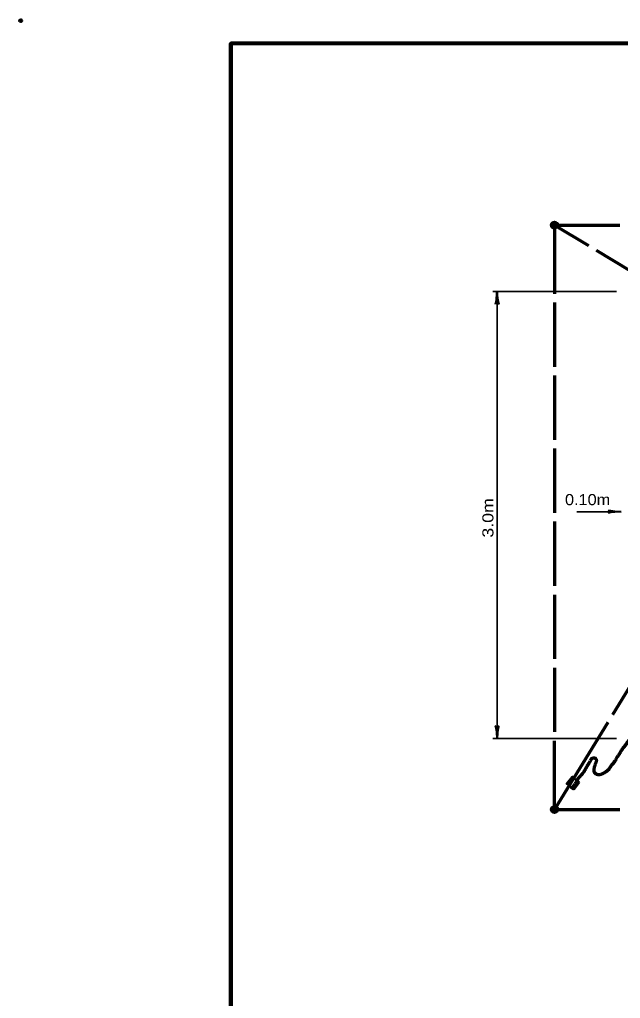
# Model space of a CAD drawing. Extents: x -30 to 826, y -11 to 533.
# Drawn here: x -29.8 to 133.1, y 268.1 to 533.4 of the extents above; entities that cross this region are included whole.
import ezdxf

# ---------------------------------------------------------------- set-up
doc = ezdxf.new("R2010")
doc.units = 0
doc.header["$LTSCALE"] = 1.2
doc.header["$PDMODE"] = 32
doc.header["$PDSIZE"] = 0.6
doc.layers.add('1', color=7, linetype='Continuous', lineweight=53)

msp = doc.modelspace()

# ---------------------------------------------------------------- hatches: boundary and pattern name
at = {"layer": '1'}
for points in [[(116.199, 477.732, 1), (114.399, 477.732, 1)], [(116.199, 319.332, 1), (114.399, 319.332, 1)]]:
    msp.add_hatch(color=256, dxfattribs=at).paths.add_polyline_path(points)

# ---------------------------------------------------------------- linework, layer by layer
at = {"layer": '1', "lineweight": 70}
for p, q in [((115.299, 477.732), (132.999, 477.732)), ((115.299, 477.732), (115.299, 459.132)), ((115.299, 477.732), (124.489, 472.18)), ((126.543, 470.94), (135.733, 465.388)), ((115.299, 456.732), (115.299, 439.332)), ((115.299, 436.932), (115.299, 419.532)), ((115.299, 417.132), (115.299, 399.732)), ((115.299, 397.332), (115.299, 379.932)), ((115.299, 377.532), (115.299, 360.132)), ((145.422, 368.559), (130.987, 344.969)), ((115.299, 357.732), (115.299, 340.332)), ((129.734, 342.922), (115.299, 319.332)), ((115.299, 319.332), (115.299, 337.932)), ((115.299, 319.332), (132.999, 319.332))]:
    msp.add_line(p, q, dxfattribs=at)
at = {"layer": '1', "lineweight": 35}
for p, q in [((132.099, 459.732), (98.499, 459.732)), ((99.699, 459.732), (99.699, 338.532)), ((133.299, 400.032), (121.299, 400.032)), ((132.099, 338.532), (98.499, 338.532))]:
    msp.add_line(p, q, dxfattribs=at)
at = {"layer": '1', "lineweight": 158}
msp.add_lwpolyline([(819.196, 527.044), (27.496, 526.944), (27.596, 0.944)], dxfattribs=at)
at = {"layer": '1'}
msp.add_lwpolyline([(121.996, 326.701), (120.525, 324.805), (118.629, 326.276), (120.1, 328.172)], close=True, dxfattribs=at)
for centre in [(115.299, 477.732), (115.299, 319.332)]:
    msp.add_circle(centre, 0.9, dxfattribs=at)
at = {"layer": '1', "lineweight": 40}
for centre, major_axis, ratio, start_param, end_param in [((99.445, 458.388), (-0.211, -2.108), 0.07063, 6.2823074, 8.5597026), ((99.445, 458.388), (-0.211, -2.108), 0.07063, 6.2823074, 8.5597026), ((100.03, 458.423), (-0.187, 2.143), 0.122415, 0.8963533, 3.1415927), ((100.03, 458.423), (-0.187, 2.143), 0.122415, 0.8963533, 3.1415927), ((131.989, 399.701), (2.143, 0.187), 0.122415, 0.8963533, 3.1415927), ((131.989, 399.701), (2.143, 0.187), 0.122415, 0.8963533, 3.1415927), ((131.954, 400.286), (2.108, -0.211), 0.07063, 3.1407148, 5.41811), ((131.954, 400.286), (2.108, -0.211), 0.07063, 3.1407148, 5.41811), ((99.367, 339.842), (0.187, -2.143), 0.122415, 0.8963533, 3.1415927), ((99.953, 339.877), (0.211, 2.108), 0.07063, 6.2823074, 8.5597026)]:
    msp.add_ellipse(centre, major_axis=major_axis, ratio=ratio, start_param=start_param, end_param=end_param, dxfattribs=at)
at = {"layer": '1', "lineweight": 70}
for points in [[(139.942, 344.134), (139.815, 343.853), (139.688, 343.604), (139.562, 343.417), (139.405, 343.262), (139.185, 343.044), (138.996, 342.857), (138.839, 342.733), (138.619, 342.578), (138.399, 342.392), (138.179, 342.174), (138.021, 341.956), (137.832, 341.77), (137.674, 341.458), (137.548, 341.302), (137.422, 341.115), (137.327, 340.929), (137.138, 340.617), (136.979, 340.274), (136.79, 339.962), (136.632, 339.744), (136.443, 339.433), (136.222, 339.059), (135.97, 338.748), (135.686, 338.374), (135.465, 338.063), (135.339, 337.907), (135.213, 337.72), (134.993, 337.471), (134.867, 337.316), (134.772, 337.097), (134.551, 336.849), (134.425, 336.662), (134.268, 336.444), (134.141, 336.288), (133.953, 336.102), (133.827, 335.915), (133.637, 335.634), (133.511, 335.447), (133.322, 335.23), (133.196, 334.98), (133.038, 334.731), (132.848, 334.42), (132.69, 334.17), (132.532, 333.89), (132.344, 333.672), (132.186, 333.392), (132.027, 333.08), (131.901, 332.862), (131.775, 332.644), (131.586, 332.394), (131.459, 332.176), (131.333, 331.99), (131.275, 331.903)], [(126.583, 332.99), (126.502, 333.057), (126.297, 333.185), (126.092, 333.211), (125.886, 333.236), (125.656, 333.211), (125.425, 333.108), (125.245, 332.98), (125.04, 332.62), (124.912, 332.364), (124.758, 332.081), (124.604, 331.774), (124.424, 331.543), (124.322, 331.363), (124.142, 331.106), (124.014, 330.901), (123.834, 330.619), (123.706, 330.362), (123.604, 330.131), (123.398, 329.798), (123.219, 329.541), (123.091, 329.336), (122.86, 329.079), (122.68, 328.822), (122.475, 328.617), (122.218, 328.36), (122.039, 328.104), (121.808, 327.847), (121.603, 327.565), (121.5, 327.385), (121.346, 327.129), (121.218, 326.923), (121.115, 326.718), (120.962, 326.462), (120.808, 326.231), (120.602, 325.923), (120.423, 325.64), (120.243, 325.409), (120.038, 325.127), (119.884, 324.922), (119.809, 324.789)], [(126.583, 332.99), (126.594, 332.784), (126.626, 332.577), (126.562, 332.362), (126.499, 332.13), (126.419, 331.883), (126.339, 331.628), (126.244, 331.365), (126.172, 331.166), (126.092, 330.935), (126.029, 330.712), (125.981, 330.505), (125.957, 330.282), (125.965, 330.059), (125.971, 329.995)], [(131.545, 332.268), (131.441, 332.14), (131.252, 331.891), (131.094, 331.704), (130.937, 331.517), (130.748, 331.299), (130.559, 331.05), (130.433, 330.863), (130.275, 330.646), (130.085, 330.334), (129.959, 330.147), (129.802, 330.023), (129.645, 329.899), (129.425, 329.712), (129.237, 329.557), (129.079, 329.433), (128.734, 329.216), (128.483, 329.093), (128.232, 328.938), (128.013, 328.845), (127.731, 328.753), (127.449, 328.723), (127.199, 328.725), (126.917, 328.757), (126.605, 328.884), (126.294, 329.105), (126.139, 329.356), (126.015, 329.544), (125.985, 329.826), (125.971, 329.995)]]:
    msp.add_spline(points, degree=3, dxfattribs=at)
at = {"layer": '1'}
msp.add_point((-29.504, 533.144), dxfattribs=at)

# ---------------------------------------------------------------- texts
at = {"layer": '1', "width": 1.2}
msp.add_text('3.0m', height=3, rotation=90, dxfattribs=at).set_placement((98.695, 392.988))
at = {"layer": '1', "width": 1.1}
msp.add_text('0.10m', height=3, dxfattribs=at).set_placement((118.11, 401.801))

doc.saveas('drawing.dxf')
